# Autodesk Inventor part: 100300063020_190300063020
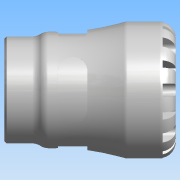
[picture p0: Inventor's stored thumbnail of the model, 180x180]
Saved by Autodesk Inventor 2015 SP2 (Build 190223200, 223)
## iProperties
Created: 2016-12
Part Number: 100300063020_190300063020
Material: PVC-Piping
Description: PLASSON FEMALE ADAPTOR 63X2" SERIES 1
Document SubType Name: Modeling
Designer: KIM
Mass: 664.223 g
Surface Area: 733.008 cm^2
Volume: 474.445 cm^3
Density: 1.4 g/cm^3
Appearance: Smooth - White
Author: KIM
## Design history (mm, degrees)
derived "1003.ipt"
feature "Solid1::1003.ipt"
tag "TaggingFeature1"
body "Solid1"
other parameters: "d0" = 129, "d1" = 37.8, "d2" = 63, "d3" = 78.75, "d4" = 103, "d8" = 87.55, "d13" = 9.7, "d14" = 9.7, "d15" = 0, "d17" = 360 deg, "d19" = 8 deg, "d20" = 1.26, "d21" = 1.26, "d22" = 8 deg, "d24" = 0, "d26" = 360 deg, "d32" = 10.3, "d33" = 10.3, "d39" = 1.69968, "d42" = 56.656, "d43" = 80.34, "d46" = 5.25, "d47" = 29, "d48" = 53.8232, "d50" = 3.3, "d51" = 1.03, "d54" = 22.05, "d55" = 13.86, "d57" = 19.012, "d58" = 0, "d68" = 360 deg, "d72" = 1.26, "d74" = 0, "d76" = 18.7425, "d_" = 63, "E_" = 103, "H_" = 129, "Rp" = 56.656, "l_2" = 29, "d9" = 12.125, "d11" = 103, "d12" = 78.75
